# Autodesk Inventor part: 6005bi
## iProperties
Shininess: 64.0
Length Units: 11269
Angle Units: 11279
Time Units: 11290
Mass Units: 11283
Length Display Precision: 3
Angle Display Precision: 2
Compacted: True
Part Number: 6005bi
Document SubType Name: Modeling
Created: 2004-09
Material: Par défaut
Density: 1 g/cm^3
Density: 0.0
Volumn: 0.0
Area: 0.0
PropertySet Name: Model Information
Control State: 0
Master: False
Checked Out: False
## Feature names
1. Révolution1 [Revolution]
